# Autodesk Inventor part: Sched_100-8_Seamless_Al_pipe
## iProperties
Shininess: 64.0
Length Units: 11272
Angle Units: 11279
Time Units: 11290
Mass Units: 11286
Length Display Precision: 3
Angle Display Precision: 2
Compacted: True
Part Number: Sched_100-8_Seamless_Al_pipe
Document SubType Name: Modeling
Created: 2005-05
Designer: John Blackburn
Manufacturer: Standard
Standards Organization: Custom
Material: Aluminum-6061
Density: 0.0
Volumn: 0.0
Area: 0.0
PropertySet Name: Model Information
Control State: 0
Master: False
Checked Out: False
Author: John Blackburn
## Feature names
1. Extrusion1
